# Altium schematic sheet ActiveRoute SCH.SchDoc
size 431 x 279 mm; Organization: Altium Limited; Address1: L3, 12a Rodborough Rd; Address2: Frenchs Forest; Address3: NSW; Address4: Australia 2086
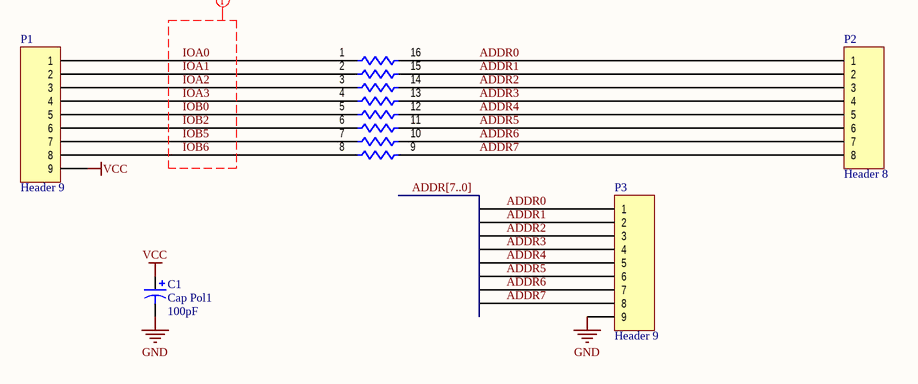
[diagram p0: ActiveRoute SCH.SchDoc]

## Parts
C1  Cap Pol1  value 100pF  [RB7.6-15]
P1  Header 9  [HDR1X9]
P2  Header 8  [HDR1X8]
P3  Header 9  [HDR1X9]
R1  Res Pack1  [SOIC16_N]  (value not drawn)  (parts A,B,C,D,E,F,G,H of 8)

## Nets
GND: C1.2 P3.9
VCC: C1.1 P1.9
ADDR0: P2.1 P3.1 R1.16
ADDR1: P2.2 P3.2 R1.15
ADDR2: P2.3 P3.3 R1.14
ADDR3: P2.4 P3.4 R1.13
ADDR4: P2.5 P3.5 R1.12
ADDR5: P2.6 P3.6 R1.11
ADDR6: P2.7 P3.7 R1.10
ADDR7: P2.8 P3.8 R1.9
IOA0: P1.1 R1.1
IOA1: P1.2 R1.2
IOA2: P1.3 R1.3
IOA3: P1.4 R1.4
IOB0: P1.5 R1.5
IOB2: P1.6 R1.6
IOB5: P1.7 R1.7
IOB6: P1.8 R1.8

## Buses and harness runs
bus ADDR[7..0]

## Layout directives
net class P1nets: IOA0, IOA1, IOA2, IOA3, IOB0, IOB2, IOB5, IOB6

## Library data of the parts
C1 = Cap Pol1: Polarized Capacitor (Radial)
P1 P3 = Header 9: Header, 9-Pin
P2 = Header 8: Header, 8-Pin
R1 = Res Pack1: Isolated Resistor Network - Parts; Sim Note: Enter the Resistance value into parameter field.; Value: 1K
